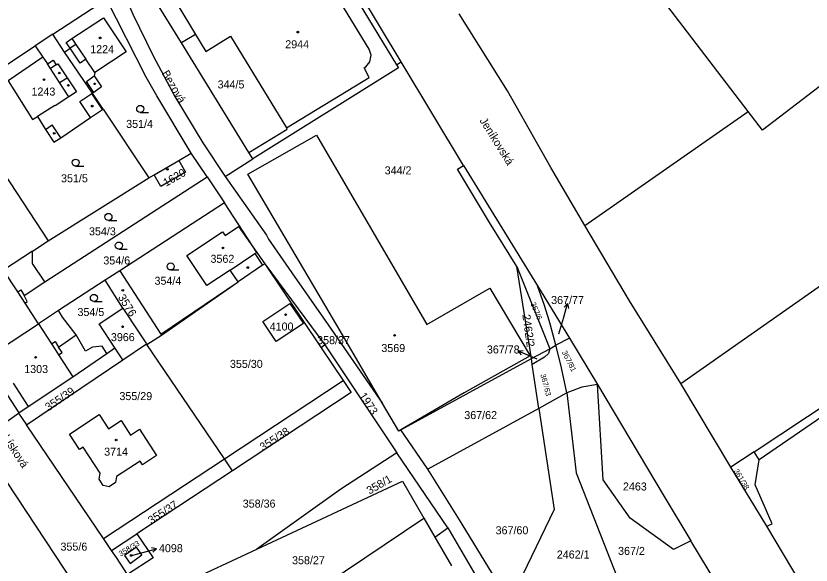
# Model space of a CAD drawing. Extents: x -679220 to -673243, y -1075091 to -1066557.
# Drawn here: x -675822.5 to -675653.7, y -1072672.3 to -1072555.7 of the extents above; entities that cross this region are included whole.
import ezdxf

# ---------------------------------------------------------------- set-up
doc = ezdxf.new("R2010")
doc.units = 0
for name, color, linetype in [('Hranice parcel', 7, 'Continuous'), ('Parcelní čísla', 7, 'Continuous'), ('Pop  PČ popisy', 7, 'Continuous'), ('Vnitřní kresba', 7, 'Continuous'), ('Značky budov', 7, 'Continuous'), ('Značky kultur', 7, 'Continuous')]:
    doc.layers.add(name, color=color, linetype=linetype)

msp = doc.modelspace()

# ---------------------------------------------------------------- linework, layer by layer
at = {"layer": 'Hranice parcel'}
for p, q in [((-675814.67, -1072559.62), (-675803.25, -1072552.13)), ((-675814.67, -1072559.62), (-675818.38, -1072562.07)), ((-675812.16, -1072563.42), (-675814.67, -1072559.62)), ((-675784.36, -1072559.7), (-675787.38, -1072561.47)), ((-675835.5, -1072573.38), (-675818.38, -1072562.07)), ((-675773.06, -1072584.73), (-675787.38, -1072561.47)), ((-675806.23, -1072572.14), (-675812.16, -1072563.42)), ((-675741.69, -1072566.13), (-675740.73, -1072565.51)), ((-675727.47, -1072587.46), (-675740.73, -1072565.51)), ((-675803.97, -1072575.5), (-675806.23, -1072572.14)), ((-675803.97, -1072575.5), (-675794.32, -1072590.13)), ((-675701.72, -1072600.24), (-675667.06, -1072576)), ((-675828.13, -1072584.48), (-675815.64, -1072603.44)), ((-675787.9, -1072586.41), (-675785.29, -1072584.89)), ((-675781.92, -1072589.91), (-675785.29, -1072584.89)), ((-675772.22, -1072586.09), (-675773.06, -1072584.73)), ((-675793.18, -1072589.47), (-675787.9, -1072586.41)), ((-675778.12, -1072589.82), (-675772.22, -1072586.09)), ((-675727.47, -1072587.46), (-675711.79, -1072613.04)), ((-675816.38, -1072612.2), (-675781.92, -1072589.91)), ((-675815.64, -1072603.44), (-675794.32, -1072590.13)), ((-675794.32, -1072590.13), (-675793.18, -1072589.47)), ((-675781.92, -1072589.91), (-675778.23, -1072595.42)), ((-675778.23, -1072595.42), (-675800.44, -1072609.81)), ((-675771.37, -1072605.96), (-675778.23, -1072595.42)), ((-675818.97, -1072605.64), (-675815.64, -1072603.44)), ((-675771.37, -1072605.96), (-675769.7, -1072608.36)), ((-675769.7, -1072608.36), (-675756.9, -1072625.54)), ((-675769.7, -1072608.36), (-675757.7, -1072626.16)), ((-675713.09, -1072628.47), (-675716.16, -1072608.9)), ((-675716.16, -1072608.9), (-675709.19, -1072626.38)), ((-675800.44, -1072609.81), (-675803.55, -1072611.82)), ((-675803.55, -1072611.82), (-675813.44, -1072618.26)), ((-675799.82, -1072617.78), (-675803.55, -1072611.82)), ((-675711.79, -1072613.04), (-675705.02, -1072624.09)), ((-675710.28, -1072617.22), (-675711.79, -1072613.04)), ((-675813.44, -1072618.26), (-675817.73, -1072621.05)), ((-675827.23, -1072627.33), (-675817.73, -1072621.05)), ((-675707.87, -1072625.64), (-675709.01, -1072621.39)), ((-675705.02, -1072624.09), (-675707.87, -1072625.64)), ((-675705.02, -1072624.09), (-675699.06, -1072633.96)), ((-675803.17, -1072627.37), (-675801.49, -1072626.15)), ((-675799.82, -1072628.71), (-675801.49, -1072626.15)), ((-675799.82, -1072628.71), (-675794.78, -1072625.3)), ((-675794.78, -1072625.3), (-675794.68, -1072625.45)), ((-675778.2, -1072649.75), (-675794.68, -1072625.45)), ((-675756.9, -1072625.54), (-675757.7, -1072626.16)), ((-675757.7, -1072626.16), (-675753.01, -1072633.12)), ((-675756.9, -1072625.54), (-675741.62, -1072648.47)), ((-675713.09, -1072628.47), (-675709.19, -1072626.38)), ((-675709.19, -1072626.38), (-675709.48, -1072627.36)), ((-675709.19, -1072626.38), (-675707.87, -1072625.64)), ((-675707.14, -1072628.63), (-675707.87, -1072625.64)), ((-675709.48, -1072627.36), (-675710.33, -1072628.17)), ((-675829.24, -1072628.63), (-675821.87, -1072639.98)), ((-675820.26, -1072642.52), (-675799.82, -1072628.71)), ((-675740.8, -1072643.6), (-675713.09, -1072628.47)), ((-675712.91, -1072629.68), (-675713.09, -1072628.47)), ((-675710.33, -1072628.17), (-675712.91, -1072629.68)), ((-675711.53, -1072639.04), (-675712.91, -1072629.68)), ((-675706.71, -1072630.41), (-675707.14, -1072628.63)), ((-675705.54, -1072635.75), (-675706.71, -1072630.41)), ((-675778.2, -1072649.75), (-675753.01, -1072633.12)), ((-675670.76, -1072651.48), (-675681.36, -1072633.74)), ((-675705.54, -1072635.75), (-675711.53, -1072639.04)), ((-675711.53, -1072639.04), (-675735.05, -1072651.95)), ((-675821.95, -1072640.04), (-675821.87, -1072639.98)), ((-675821.95, -1072640.04), (-675820.26, -1072642.52)), ((-675803.88, -1072666.62), (-675820.26, -1072642.52)), ((-675735.05, -1072651.95), (-675740.8, -1072643.6)), ((-675793.88, -1072700.75), (-675830.26, -1072645.77)), ((-675665.8, -1072648.21), (-675670.76, -1072651.48)), ((-675664.77, -1072649.96), (-675665.8, -1072648.21)), ((-675803.88, -1072666.62), (-675778.2, -1072649.75)), ((-675776.5, -1072652.25), (-675778.2, -1072649.75)), ((-675730.83, -1072664.33), (-675741.62, -1072648.47)), ((-675663.08, -1072664), (-675670.76, -1072651.48)), ((-675776.5, -1072652.25), (-675796.86, -1072665.66)), ((-675770.31, -1072685.33), (-675735.9, -1072662.3)), ((-675735.9, -1072662.3), (-675733.57, -1072666.33)), ((-675733.57, -1072666.33), (-675730.83, -1072664.33)), ((-675730.83, -1072664.33), (-675717.25, -1072687.67)), ((-675651.88, -1072682.89), (-675663.08, -1072664)), ((-675802.19, -1072669.17), (-675803.88, -1072666.62)), ((-675802.19, -1072669.17), (-675796.86, -1072665.66)), ((-675733.57, -1072666.33), (-675730.05, -1072672.42)), ((-675664.18, -1072692.04), (-675679.25, -1072667.1)), ((-675795.06, -1072679.9), (-675771.36, -1072668.86))]:
    msp.add_line(p, q, dxfattribs=at)
for points in [[(-675667.06, -1072576), (-675695.35, -1072538.98), (-675624.32, -1072484.68), (-675612.98, -1072499.47), (-675609.59, -1072496.88), (-675597.62, -1072512.63), (-675601, -1072515.19), (-675594.8, -1072523.34)], [(-675740.73, -1072565.51), (-675767.49, -1072520.97), (-675770.65, -1072515.77)], [(-675594.8, -1072523.34), (-675593.03, -1072525.66), (-675664.03, -1072579.96), (-675667.06, -1072576)], [(-675787.38, -1072561.47), (-675796.29, -1072547), (-675765.67, -1072526.64), (-675741.69, -1072566.13)], [(-675681.36, -1072633.74), (-675619.75, -1072590.56), (-675551.48, -1072539.61)], [(-675804, -1072540.66), (-675797.68, -1072555.37), (-675793.38, -1072564.25), (-675788.79, -1072572.83), (-675782.79, -1072582.7), (-675778.12, -1072589.82)], [(-675765.07, -1072579.51), (-675747.5, -1072568.78), (-675748.6, -1072566.77), (-675748.24, -1072566.53), (-675747.35, -1072565.49), (-675747.06, -1072564.07), (-675747.52, -1072562.8), (-675755.12, -1072550.33), (-675757.07, -1072548.08), (-675759.72, -1072546.69), (-675762.77, -1072546.27), (-675765.68, -1072547.04), (-675766.55, -1072547.48), (-675767.1, -1072546.79), (-675775.96, -1072552.09), (-675778.73, -1072547.69), (-675788.15, -1072553.46), (-675784.36, -1072559.7)], [(-675785.29, -1072584.89), (-675792.61, -1072572.7), (-675794.85, -1072568.73), (-675803.25, -1072552.13)], [(-675701.72, -1072600.24), (-675708.95, -1072587.93), (-675718.18, -1072571.67), (-675728.38, -1072555.32)], [(-675812.16, -1072563.42), (-675810.97, -1072562.61), (-675811.81, -1072561.37), (-675810.61, -1072560.56), (-675803.91, -1072556.18), (-675799.13, -1072563.39), (-675805.74, -1072567.74), (-675805.92, -1072568.44), (-675804.32, -1072570.79), (-675805.95, -1072571.98), (-675806.23, -1072572.14)], [(-675784.36, -1072559.7), (-675782.18, -1072563.28), (-675776.93, -1072560.08), (-675765.07, -1072579.51)], [(-675818.38, -1072562.07), (-675816.78, -1072564.49), (-675824.16, -1072569.53), (-675818.99, -1072577.73), (-675817.94, -1072577.07), (-675816.22, -1072579.82), (-675814.42, -1072582.56), (-675812.99, -1072581.62), (-675806.66, -1072577.33), (-675804.14, -1072575.61), (-675803.97, -1072575.5)], [(-675741.69, -1072566.13), (-675741.3, -1072566.77), (-675772.22, -1072586.09)], [(-675665.8, -1072648.21), (-675615.05, -1072614.65), (-675561.74, -1072575.37), (-675553.38, -1072569.02)], [(-675553.46, -1072570.33), (-675561.17, -1072576.17), (-675614.5, -1072615.46), (-675664.77, -1072649.96)], [(-675773.06, -1072584.73), (-675764.94, -1072579.76), (-675765.07, -1072579.51)], [(-675773.24, -1072589.33), (-675758.73, -1072581.03), (-675735.28, -1072621.21), (-675721.91, -1072613.54), (-675713.37, -1072627.84)], [(-675787.9, -1072586.41), (-675786.47, -1072588.87), (-675791.75, -1072591.93), (-675793.18, -1072589.47)], [(-675716.16, -1072608.9), (-675721.95, -1072599.57), (-675728.8, -1072588.26), (-675727.47, -1072587.46)], [(-675744.68, -1072637.98), (-675753.65, -1072622.57), (-675773.24, -1072589.33)], [(-675778.12, -1072589.82), (-675769.33, -1072602.25), (-675768.91, -1072603.09), (-675763.93, -1072610.26), (-675756.19, -1072621.29), (-675744.68, -1072637.98)], [(-675775.35, -1072612.18), (-675777.04, -1072609.67), (-675781.96, -1072612.97), (-675786.22, -1072606.6), (-675778.62, -1072601.58), (-675778.11, -1072602.34), (-675775.22, -1072600.44), (-675771.37, -1072605.96)], [(-675681.36, -1072633.74), (-675692.25, -1072616.23), (-675701.72, -1072600.24)], [(-675818.97, -1072605.64), (-675825.11, -1072609.69), (-675834.63, -1072615.99)], [(-675816.38, -1072612.2), (-675818.95, -1072608.26), (-675818.97, -1072605.64)], [(-675769.7, -1072608.36), (-675770.13, -1072608.65), (-675775.35, -1072612.18)], [(-675800.44, -1072609.81), (-675791.75, -1072623.25), (-675775.35, -1072612.18)], [(-675817.73, -1072621.05), (-675820.56, -1072616.71), (-675820.08, -1072616.32), (-675820.73, -1072615.08), (-675816.38, -1072612.2)], [(-675794.68, -1072625.45), (-675791.62, -1072623.45), (-675775.35, -1072612.18)], [(-675801.49, -1072626.15), (-675804.82, -1072621.07), (-675799.82, -1072617.78)], [(-675799.82, -1072617.78), (-675796.51, -1072622.75), (-675794.78, -1072625.3)], [(-675764.35, -1072616.75), (-675761.48, -1072620.99), (-675767.23, -1072624.83), (-675770.1, -1072620.57), (-675764.35, -1072616.75)], [(-675709.01, -1072621.39), (-675709.3, -1072620.35), (-675710.28, -1072617.22)], [(-675803.17, -1072627.37), (-675804.21, -1072625.83), (-675806.21, -1072626.01), (-675807.72, -1072626.87), (-675809.7, -1072623.41), (-675812.58, -1072619.69), (-675813.44, -1072618.26)], [(-675821.87, -1072639.98), (-675819.88, -1072638.64), (-675810.44, -1072632.29), (-675803.17, -1072627.37)], [(-675713.37, -1072627.84), (-675727.35, -1072635.73), (-675740.8, -1072643.6)], [(-675753.01, -1072633.12), (-675751.33, -1072635.67), (-675776.5, -1072652.25)], [(-675699.06, -1072633.96), (-675702.41, -1072634.54), (-675705.54, -1072635.75)], [(-675699.06, -1072633.96), (-675685.11, -1072657.39), (-675679.25, -1072667.1)], [(-675679.25, -1072667.1), (-675682.89, -1072668.96), (-675692.13, -1072662.31), (-675697.82, -1072654.15), (-675699.06, -1072633.96)], [(-675705.54, -1072635.75), (-675703.56, -1072652.66), (-675694.79, -1072675.02)], [(-675740.8, -1072643.6), (-675741.25, -1072643.86), (-675744.68, -1072637.98)], [(-675711.53, -1072639.04), (-675708.25, -1072660.5), (-675715, -1072674.38)], [(-675830.26, -1072645.77), (-675825.98, -1072642.83), (-675821.95, -1072640.04)], [(-675796.14, -1072650.25), (-675801.15, -1072653.47), (-675801.39, -1072654.75), (-675802.74, -1072655.67), (-675803.98, -1072655.38), (-675804.86, -1072654.03), (-675804.63, -1072652.75), (-675808.25, -1072647.25), (-675809, -1072647.74), (-675811.12, -1072644.49), (-675804.82, -1072640.35), (-675802.87, -1072643.34), (-675800.18, -1072641.58), (-675798.16, -1072644.67), (-675796.26, -1072643.44), (-675792.63, -1072649.03), (-675795.64, -1072650.99), (-675796.14, -1072650.25)], [(-675741.62, -1072648.47), (-675753.53, -1072656.14), (-675771.36, -1072668.86)], [(-675663.08, -1072664), (-675661.98, -1072663.5), (-675665.57, -1072655.27), (-675664.77, -1072649.96)], [(-675700.65, -1072714.05), (-675705.76, -1072702.93), (-675710.18, -1072693.37), (-675720.03, -1072676.29), (-675728.35, -1072662.68), (-675735.05, -1072651.95)], [(-675771.36, -1072668.86), (-675740.47, -1072654.46), (-675735.9, -1072662.3)], [(-675796.86, -1072665.66), (-675793.4, -1072670.71), (-675798.81, -1072674.26)], [(-675796.93, -1072668.49), (-675799.47, -1072670.2), (-675798.24, -1072671.9), (-675795.76, -1072670.11), (-675796.93, -1072668.49)], [(-675798.81, -1072674.26), (-675801.17, -1072670.66), (-675802.19, -1072669.17)]]:
    msp.add_lwpolyline(points, dxfattribs=at)
at = {"layer": 'Pop  PČ popisy'}
for p, q in [((-675706.23, -1072619.63), (-675705.4, -1072616.75)), ((-675705.4, -1072616.75), (-675706.16, -1072617.57)), ((-675705.4, -1072616.75), (-675705.2, -1072617.85)), ((-675707.26, -1072623.23), (-675706.23, -1072619.63)), ((-675715.93, -1072626.8), (-675714.81, -1072626.75)), ((-675713.19, -1072628.02), (-675715.93, -1072626.8)), ((-675715.93, -1072626.8), (-675715.22, -1072627.66)), ((-675711.89, -1072628.58), (-675713.19, -1072628.02)), ((-675792.63, -1072668.8), (-675793.73, -1072668.58)), ((-675797.67, -1072670.17), (-675795.53, -1072669.58)), ((-675795.53, -1072669.58), (-675792.63, -1072668.8)), ((-675792.63, -1072668.8), (-675793.47, -1072669.55))]:
    msp.add_line(p, q, dxfattribs=at)
at = {"layer": 'Vnitřní kresba'}
for p, q in [((-675810.61, -1072560.56), (-675809.77, -1072561.8)), ((-675809.77, -1072561.8), (-675810.97, -1072562.61)), ((-675809.77, -1072561.8), (-675807.63, -1072564.96)), ((-675808.83, -1072565.77), (-675810.97, -1072562.61)), ((-675816.78, -1072564.49), (-675815.83, -1072565.93)), ((-675815.83, -1072565.93), (-675814.58, -1072565.11)), ((-675814.58, -1072565.11), (-675813.93, -1072566.1)), ((-675807.63, -1072564.96), (-675808.83, -1072565.77)), ((-675805.74, -1072567.74), (-675807.63, -1072564.96)), ((-675815.19, -1072566.92), (-675815.83, -1072565.93)), ((-675813.93, -1072566.1), (-675815.19, -1072566.92)), ((-675813.22, -1072569.91), (-675815.19, -1072566.92)), ((-675813.93, -1072566.1), (-675813.59, -1072565.88)), ((-675813.59, -1072565.88), (-675811.63, -1072568.87)), ((-675813.22, -1072569.91), (-675811.63, -1072568.87)), ((-675811.63, -1072568.87), (-675809.67, -1072571.86)), ((-675807.51, -1072569.65), (-675805.92, -1072568.44)), ((-675811.26, -1072572.9), (-675813.22, -1072569.91)), ((-675805.95, -1072571.98), (-675807.51, -1072569.65)), ((-675809.67, -1072571.86), (-675811.26, -1072572.9)), ((-675808.91, -1072573.88), (-675806.38, -1072572.23)), ((-675804.14, -1072575.61), (-675806.38, -1072572.23)), ((-675811.26, -1072572.9), (-675814.19, -1072574.84)), ((-675806.66, -1072577.33), (-675808.91, -1072573.88)), ((-675814.25, -1072574.74), (-675817.94, -1072577.07)), ((-675814.19, -1072574.84), (-675814.25, -1072574.74)), ((-675816.22, -1072579.82), (-675814.79, -1072578.88)), ((-675812.99, -1072581.62), (-675814.79, -1072578.88)), ((-675777.04, -1072609.67), (-675771.78, -1072606.14)), ((-675771.78, -1072606.14), (-675771.37, -1072605.96)), ((-675771.78, -1072606.14), (-675770.13, -1072608.65)), ((-675822.11, -1072614.31), (-675825.11, -1072609.69)), ((-675822.11, -1072614.31), (-675821.49, -1072613.9)), ((-675820.56, -1072616.71), (-675822.11, -1072614.31)), ((-675821.49, -1072613.9), (-675820.73, -1072615.08)), ((-675817.73, -1072621.05), (-675814.97, -1072625.32)), ((-675813.44, -1072626), (-675809.7, -1072623.41)), ((-675814.97, -1072625.32), (-675814.2, -1072624.82)), ((-675814.97, -1072625.32), (-675814.2, -1072626.49)), ((-675814.2, -1072624.82), (-675813.44, -1072626)), ((-675812.67, -1072627.18), (-675813.44, -1072626)), ((-675814.2, -1072626.49), (-675813.44, -1072627.67)), ((-675813.44, -1072627.67), (-675812.67, -1072627.18)), ((-675813.44, -1072627.67), (-675810.44, -1072632.29)), ((-675823.09, -1072633.68), (-675819.88, -1072638.64))]:
    msp.add_line(p, q, dxfattribs=at)
at = {"layer": 'Značky budov'}
for centre in [(-675804.62, -1072560.41), (-675762.66, -1072559.19), (-675816.55, -1072569.26), (-675813.29, -1072567.86), (-675811.36, -1072570.48), (-675805.77, -1072570.16), (-675806.31, -1072574.88), (-675814.37, -1072580.65), (-675790.33, -1072588.3), (-675778.53, -1072604.98), (-675773.28, -1072609.14), (-675799.82, -1072613.97), (-675765.25, -1072619.14), (-675799.85, -1072621.7), (-675742.11, -1072623.53), (-675818.32, -1072628.2), (-675801.22, -1072645.73), (-675798.03, -1072670.23)]:
    msp.add_circle(centre, 0.175, dxfattribs=at)
at = {"layer": 'Značky kultur'}
for p, q in [((-675796.11, -1072576.22), (-675794.36, -1072576.22)), ((-675809.83, -1072587.62), (-675808.08, -1072587.62)), ((-675802.86, -1072599.14), (-675801.11, -1072599.14)), ((-675800.65, -1072605.22), (-675798.9, -1072605.22)), ((-675789.65, -1072609.65), (-675787.9, -1072609.65)), ((-675805.95, -1072616.33), (-675804.2, -1072616.33))]:
    msp.add_line(p, q, dxfattribs=at)
for centre in [(-675796.11, -1072575.47), (-675809.83, -1072586.87), (-675802.86, -1072598.39), (-675800.65, -1072604.47), (-675789.65, -1072608.9), (-675805.95, -1072615.58)]:
    msp.add_circle(centre, 0.75, dxfattribs=at)

# ---------------------------------------------------------------- texts
at = {"layer": 'Parcelní čísla'}
for s, p in [('1224', (-675806.73, -1072563.66)), ('2944', (-675765.33, -1072562.61)), ('344/5', (-675779.69, -1072571.13)), ('1243', (-675819.19, -1072572.65)), ('351/4', (-675799.1, -1072579.51)), ('344/2', (-675744.23, -1072589.37)), ('351/5', (-675812.92, -1072591.05)), ('354/3', (-675806.99, -1072602.3)), ('354/6', (-675803.94, -1072608.48)), ('3562', (-675781.2, -1072608.13)), ('354/4', (-675793.08, -1072612.79)), ('367/77', (-675708.89, -1072616.88)), ('354/5', (-675809.43, -1072619.42)), ('4100', (-675768.64, -1072622.5)), ('3966', (-675802.34, -1072624.75)), ('358/37', (-675758.56, -1072625.39)), ('3569', (-675744.93, -1072627.07)), ('367/78', (-675722.53, -1072627.37)), ('1303', (-675820.74, -1072631.52)), ('355/30', (-675777.07, -1072630.43)), ('355/29', (-675800.53, -1072637.26)), ('367/62', (-675727.33, -1072641.29)), ('3714', (-675803.77, -1072649.05)), ('2463', (-675693.65, -1072656.44)), ('358/36', (-675774.35, -1072660.07)), ('367/60', (-675720.68, -1072665.73)), ('355/6', (-675813.04, -1072669.2)), ('4098', (-675792.14, -1072669.53)), ('367/2', (-675694.68, -1072670.11)), ('358/27', (-675763.88, -1072672.09)), ('2462/1', (-675707.69, -1072670.87))]:
    msp.add_text(s, height=1.7, dxfattribs=at).set_placement(p)
for s, height, rotation, p in [('1620', 1.7, 30, (-675790.64, -1072592.02)), ('3576', 1.7, 302, (-675800.91, -1072615.45)), ('367/6', 1.139, 293, (-675713.31, -1072616.78)), ('2462/2', 1.7, 278, (-675715.01, -1072619.2)), ('367/81', 1.139, 297, (-675706.66, -1072627.09)), ('367/63', 1.139, 285, (-675711.19, -1072631.85)), ('355/39', 1.7, 34, (-675815.6, -1072639.65)), ('1973', 1.7, 303, (-675749.73, -1072636.32)), ('355/38', 1.7, 33, (-675770.06, -1072648.12)), ('358/1', 1.7, 30, (-675747.45, -1072657.34)), ('361/38', 1.14, 301, (-675670.17, -1072652.29)), ('355/37', 1.7, 33, (-675793.78, -1072663.67)), ('358/33', 1.139, 31, (-675800.25, -1072670.45))]:
    msp.add_text(s, height=height, rotation=rotation, dxfattribs=at).set_placement(p)
at = {"layer": 'Pop  PČ popisy'}
for s, rotation, p in [('Bezová', 300, (-675791.61, -1072567.89)), ('Jeníkovská', 302, (-675724.15, -1072577.96)), ('Lísková', 303, (-675825.41, -1072645.26))]:
    msp.add_text(s, height=1.7, rotation=rotation, dxfattribs=at).set_placement(p)

doc.saveas('drawing.dxf')
